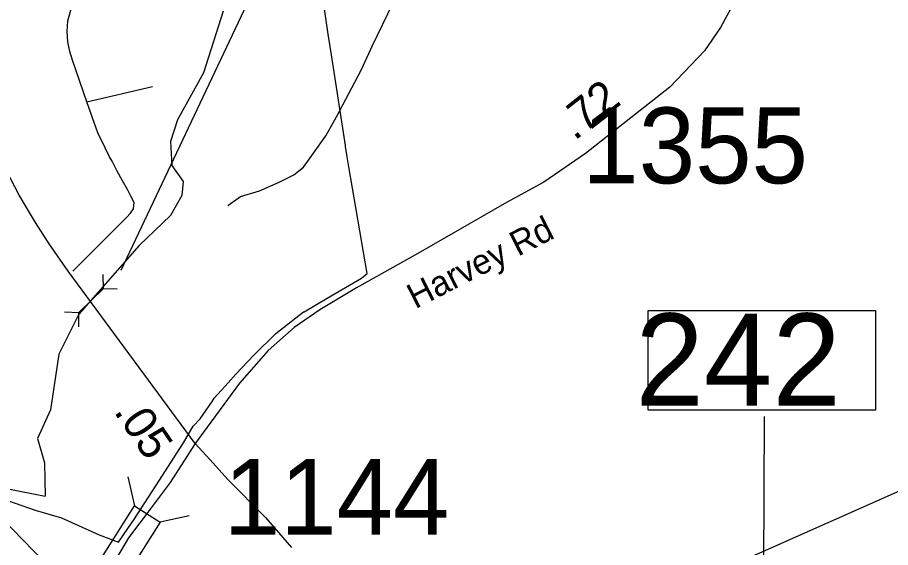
# Model space of a CAD drawing. Extents: x 1662474 to 1856135, y 779280 to 917889.
# Drawn here: x 1725630 to 1728946, y 812500 to 814512 of the extents above; entities that cross this region are included whole.
import ezdxf

# ---------------------------------------------------------------- set-up
doc = ezdxf.new("R2010")
doc.units = 0
for name, color, linetype in [('Cogo Default Point CELL', 7, 'Continuous'), ('Exist Boundary Political City Limit New', 7, 'Continuous'), ('Exist Hydrographic Creek Single Shore', 7, 'Continuous'), ('Exist Hydrographic Misc Water Feature', 7, 'Continuous'), ('Exist Road Non-System Type 51', 7, 'Continuous'), ('Exist Road Primary Interstate Structure Standard Bridge Number Label', 7, 'Continuous'), ('Exist Road Secondary Mileage Tenths English Label', 7, 'Continuous'), ('Exist Road Secondary Structure Culvert CELL', 7, 'Continuous'), ('Exist Road Secondary Structure Standard Bridge CELL', 7, 'Continuous'), ('Exist Road Secondary Type 51 Attributed', 7, 'Continuous'), ('Exist Road Secondary Type 51 Label', 7, 'Continuous'), ('Exist Vertical Profile Horizontal Axis Label Major', 7, 'Continuous'), ('Map Preparation Boundary City Limit Buffer Line', 7, 'Continuous'), ('Prop DGN Element Guardrail', 7, 'Continuous')]:
    doc.layers.add(name, color=color, linetype=linetype)

msp = doc.modelspace()

# ---------------------------------------------------------------- linework, layer by layer
at = {"layer": 'Exist Boundary Political City Limit New'}
for points in [[(1726459.6, 813157.9), (1726527.9, 813230.8), (1726611.2, 813313), (1726715.9, 813394.5), (1726719.1, 813395.2), (1726805.5, 813446.8), (1726936.2, 813522.7), (1726958.2, 813540), (1726888.6, 813945.2), (1726882, 813983.7), (1726875.9, 814022.9), (1726875.4, 814026.2), (1726821.9, 814371.1), (1726810.1, 814449.4), (1726780.2, 814648.4)], [(1725570.4, 812686.8), (1725697.1, 812642.6), (1725796.4, 812612.4), (1725939.6, 812548.4), (1726013.2, 812520.2), (1726048.6, 812572), (1726071.4, 812605.4), (1726155.4, 812734.9), (1726260.8, 812897.2), (1726296.6, 812960.6), (1726323.8, 812988.5), (1726369.5, 813053.9), (1726377.1, 813067.2), (1726417.4, 813111.6), (1726429.9, 813125.2), (1726459.6, 813157.9)], [(1725615.5, 811961.9), (1725730.1, 812446.8), (1725573.2, 812608.6)]]:
    msp.add_lwpolyline(points, dxfattribs=at)
at = {"layer": 'Exist Hydrographic Creek Single Shore'}
for points in [[(1726411.5, 814536.2), (1726335.8, 814302.9), (1726237.8, 814123.9), (1726210.8, 814042.2), (1726216, 813950.1), (1726259.4, 813890.2), (1726254.1, 813836.2), (1726210.5, 813760.1), (1726091.4, 813646.2), (1725863.2, 813385.8), (1725787.4, 813234.1), (1725754.9, 813022.3), (1725705.8, 812914.4), (1725732.2, 812821.2), (1725734.4, 812695.2)], [(1724132.9, 813654.6), (1724167, 813529.9), (1724270.6, 813327.2), (1724377.8, 813160.9), (1724481.4, 813051.4), (1724567.2, 813028.1), (1724764.6, 812968.2), (1725347.2, 812765.6), (1725471.9, 812747.2), (1725734.4, 812695.2)]]:
    msp.add_lwpolyline(points, dxfattribs=at)
at = {"layer": 'Exist Hydrographic Misc Water Feature'}
for points in [[(1727971.5, 810729.3), (1727953.4, 810973.9), (1727904.4, 811132.5), (1727891.5, 811483.9), (1727967.5, 811607.1), (1728122.6, 812112.7), (1728249.5, 812336.6), (1728392.4, 812455.2), (1729036.5, 812740.7), (1729322.5, 813027.1), (1729649.6, 813207.5), (1729955.5, 813788.8), (1730232.6, 814062.2), (1730750.5, 814990.4), (1730768.6, 815114.7), (1730737.6, 815391.1), (1730704.6, 815450.9), (1730673.6, 815684.5), (1730708.5, 815857.7)], [(1726428.4, 813798.9), (1726476.6, 813832.5), (1726548.8, 813853.9), (1726623.2, 813887.2), (1726679.4, 813914.6), (1726715.7, 813944.3), (1726754.3, 813997.9), (1726801, 814063.5), (1726841.6, 814135.2), (1726935.3, 814312.3), (1726978.2, 814405.9), (1727055.7, 814565.2)]]:
    msp.add_lwpolyline(points, dxfattribs=at)
at = {"layer": 'Exist Road Non-System Type 51'}
msp.add_line((1725893.6, 814192.4), (1726142, 814250.1), dxfattribs=at)
for points in [[(1725893.6, 814192.4), (1725838.9, 814350.4), (1725829.1, 814383.9), (1725821.2, 814420.4), (1725817.9, 814459), (1725821, 814499.2), (1725837.8, 814558.2), (1725898.9, 814690.5)], [(1725839.6, 813549.6), (1726043.6, 813753.2), (1726059.1, 813769.8), (1726070.1, 813785.5), (1726072.4, 813810.2), (1726061.9, 813830.9), (1726047, 813858.8), (1726028.4, 813892.1), (1726008.9, 813929.4), (1725989, 813966.4), (1725979.8, 813983.9), (1725962.5, 814017.2), (1725934.6, 814074.2), (1725928.1, 814092.6), (1725893.6, 814192.4)]]:
    msp.add_lwpolyline(points, dxfattribs=at)
at = {"layer": 'Exist Road Primary Interstate Structure Standard Bridge Number Label'}
msp.add_line((1728455, 810334.1), (1728467, 812998.1), dxfattribs=at)
msp.add_lwpolyline([(1728890.3, 813398.6), (1728023.8, 813398.6), (1728023.8, 813023), (1728890.3, 813023)], close=True, dxfattribs=at)
at = {"layer": 'Exist Road Secondary Structure Culvert CELL'}
for p, q in [((1725954.1, 813536.7), (1725954.8, 813482.6)), ((1725862.4, 813392.7), (1725954.8, 813482.6)), ((1726008.9, 813480.4), (1725954.8, 813482.6)), ((1725808.3, 813394.9), (1725862.4, 813392.7)), ((1725863.1, 813338.6), (1725862.4, 813392.7))]:
    msp.add_line(p, q, dxfattribs=at)
at = {"layer": 'Exist Road Secondary Structure Standard Bridge CELL'}
for p, q in [((1726048.9, 812768.3), (1726073.8, 812657.9)), ((1726282.1, 812620.9), (1726171.7, 812596))]:
    msp.add_line(p, q, dxfattribs=at)
msp.add_lwpolyline([(1726171.7, 812596), (1726039.2, 812386.5), (1725941.4, 812448.4), (1726073.8, 812657.9)], close=True, dxfattribs=at)
at = {"layer": 'Exist Road Secondary Type 51 Attributed'}
for points in [[(1728502.4, 815647.5), (1728440.4, 814946.1), (1728412.8, 814746), (1728382.8, 814643.5), (1728347.8, 814563.5), (1728299.4, 814473.8), (1728238.7, 814386.2), (1728107.3, 814248.1), (1727787.1, 813995.5), (1727628.6, 813887.7), (1727487, 813809.4), (1727150.3, 813617), (1726917.9, 813485.9), (1726778.3, 813403), (1726680.2, 813335.2), (1726582.2, 813248.5), (1726472.8, 813124.1), (1726304.8, 812895.7)], [(1726304.8, 812895.7), (1725822.9, 813549.5), (1725750.4, 813653.2), (1725698.6, 813733.7), (1725636, 813837.4), (1725585.5, 813935.5), (1725500.1, 814162.8), (1725469.7, 814269.2), (1725406.1, 814517.6)], [(1726304.8, 812895.7), (1726209.1, 812747.4), (1726137.6, 812650.3), (1726051.9, 812536.4)], [(1726304.8, 812895.7), (1726361, 812833.4), (1726428.2, 812758.2), (1726572.1, 812614.3), (1726670.5, 812499.8)], [(1726051.9, 812536.4), (1725973.1, 812404.1), (1725819.1, 812215.5), (1725678.5, 812014.9), (1725590, 811882.1)]]:
    msp.add_lwpolyline(points, dxfattribs=at)
at = {"layer": 'Exist Vertical Profile Horizontal Axis Label Major'}
msp.add_line((1726023.4, 813552.8), (1727087.2, 815803.6), dxfattribs=at)
at = {"layer": 'Map Preparation Boundary City Limit Buffer Line'}
for points in [[(1726459.6, 813157.9), (1726527.9, 813230.8), (1726611.2, 813313), (1726715.9, 813394.5), (1726719.1, 813395.2), (1726805.5, 813446.8), (1726936.2, 813522.7), (1726958.2, 813540), (1726888.6, 813945.2), (1726882, 813983.7), (1726875.9, 814022.9), (1726875.4, 814026.2), (1726821.9, 814371.1), (1726810.1, 814449.4), (1726780.2, 814648.4)], [(1725570.4, 812686.8), (1725697.1, 812642.6), (1725796.4, 812612.4), (1725939.6, 812548.4), (1726013.2, 812520.2), (1726048.6, 812572), (1726071.4, 812605.4), (1726155.4, 812734.9), (1726260.8, 812897.2), (1726296.6, 812960.6), (1726323.8, 812988.5), (1726369.5, 813053.9), (1726377.1, 813067.2), (1726417.4, 813111.6), (1726429.9, 813125.2), (1726459.6, 813157.9)], [(1725615.5, 811961.9), (1725730.1, 812446.8), (1725573.2, 812608.6)]]:
    msp.add_lwpolyline(points, dxfattribs=at)

# ---------------------------------------------------------------- texts
at = {"layer": 'Cogo Default Point CELL'}
for s, p in [('1355', (1727775.1, 813882.7)), ('1144', (1726413.2, 812548.8))]:
    msp.add_text(s, height=288, dxfattribs=at).set_placement(p)
at = {"layer": 'Exist Road Primary Interstate Structure Standard Bridge Number Label'}
msp.add_text('242', height=350, dxfattribs=at).set_placement((1727976.4, 813038.6))
at = {"layer": 'Exist Road Secondary Mileage Tenths English Label'}
msp.add_text('.05', height=125, rotation=304.1597, dxfattribs=at).set_placement((1725993.3, 813016.3))
at = {"layer": 'Exist Road Secondary Type 51 Label'}
msp.add_text('Harvey Rd', height=95, rotation=27.0601, dxfattribs=at).set_placement((1727140.9, 813404.6))
at = {"layer": 'Prop DGN Element Guardrail'}
msp.add_text('.72', height=125, rotation=38.2708, dxfattribs=at).set_placement((1727745.8, 814042.6))

doc.saveas('drawing.dxf')
